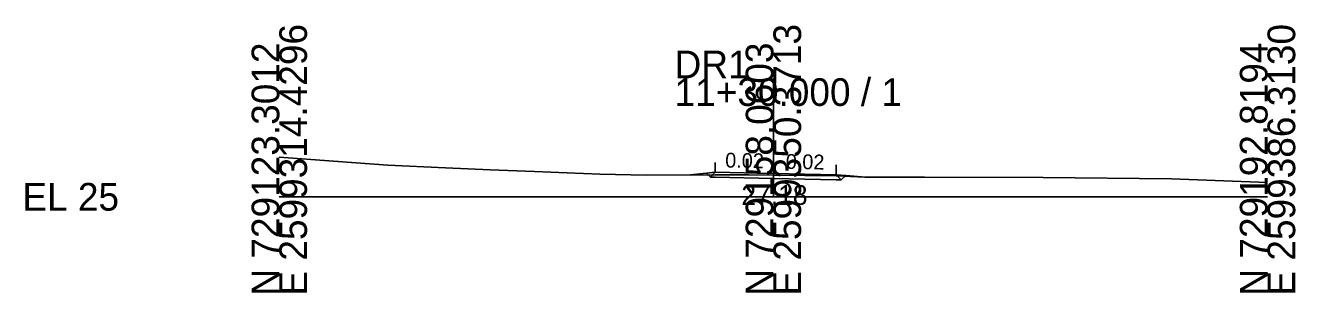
# Model space of a CAD drawing. Extents: x -26 to 1162, y -10 to 9515.
# Drawn here: x -25.7 to 102.8, y 6490.3 to 6517.3 of the extents above; entities that cross this region are included whole.
import ezdxf

# ---------------------------------------------------------------- set-up
doc = ezdxf.new("R2010")
doc.units = 0
for name, color, linetype in [('Exist Cross Section Cell', 7, 'Continuous'), ('Exist XS Center Line Elevation Label', 7, 'Continuous'), ('Exist XS Ground Line', 7, 'Continuous'), ('Prop XS Dump Level', 7, 'Continuous'), ('Prop XS EOT Tick Mark', 7, 'Continuous'), ('Prop XS Finish Grade', 7, 'Continuous'), ('Prop XS Finish Grade Earthwork', 7, 'Continuous'), ('Prop XS Finish Grade Pavement', 7, 'Continuous'), ('Prop XS Pvmt Edge Slope', 7, 'Continuous'), ('Prop XS SE Text', 7, 'Continuous'), ('Prop XS Subgrade Earthwork', 7, 'Continuous')]:
    doc.layers.add(name, color=color, linetype=linetype)

msp = doc.modelspace()

# ---------------------------------------------------------------- linework, layer by layer
at = {"layer": 'Exist Cross Section Cell'}
for p, q in [((50, 6500), (50, 6511.99)), ((0, 6500), (50, 6500)), ((50, 6500), (100, 6500))]:
    msp.add_line(p, q, dxfattribs=at)
at = {"layer": 'Exist XS Ground Line'}
msp.add_lwpolyline([(0, 6504), (10.99, 6503.2), (16.83, 6502.94), (21.35, 6502.72), (25.84, 6502.56), (32.44, 6502.28), (37.16, 6502.2), (44.12, 6502.23), (47.48, 6502.21), (50, 6502.18), (56.36, 6502.11), (59.24, 6502), (62.83, 6501.99), (65.29, 6501.99), (77.28, 6501.94), (90.28, 6501.83), (100, 6501.46)], dxfattribs=at)
at = {"layer": 'Prop XS Dump Level'}
for p, q in [((50, 6502.36), (44.11, 6502.48)), ((44.11, 6502.48), (50, 6502.36)), ((56.35, 6502.23), (50, 6502.36)), ((50, 6502.36), (56.35, 6502.23))]:
    msp.add_line(p, q, dxfattribs=at)
at = {"layer": 'Prop XS EOT Tick Mark'}
for p, q in [((44.11, 6502.48), (44.11, 6503.48)), ((56.35, 6502.23), (56.35, 6503.23))]:
    msp.add_line(p, q, dxfattribs=at)
at = {"layer": 'Prop XS Finish Grade'}
for p, q in [((44.11, 6502.48), (43.22, 6502.39)), ((56.35, 6502.23), (57.33, 6502.15))]:
    msp.add_line(p, q, dxfattribs=at)
at = {"layer": 'Prop XS Finish Grade Earthwork'}
for p, q in [((43.22, 6502.39), (41.57, 6502.22)), ((57.33, 6502.15), (59.31, 6502))]:
    msp.add_line(p, q, dxfattribs=at)
at = {"layer": 'Prop XS Finish Grade Pavement'}
for p, q in [((44.11, 6502.48), (50, 6502.36)), ((50, 6502.36), (56.35, 6502.23))]:
    msp.add_line(p, q, dxfattribs=at)
at = {"layer": 'Prop XS Pvmt Edge Slope'}
for p, q in [((44.11, 6502.48), (43.62, 6501.99)), ((43.22, 6502.39), (43.62, 6501.99)), ((56.35, 6502.23), (56.86, 6501.72)), ((57.33, 6502.15), (56.86, 6501.72))]:
    msp.add_line(p, q, dxfattribs=at)
at = {"layer": 'Prop XS Subgrade Earthwork'}
for p, q in [((43.22, 6502.39), (43.62, 6501.99)), ((44.11, 6501.98), (43.62, 6501.99)), ((50, 6501.86), (44.11, 6501.98)), ((56.35, 6501.73), (50, 6501.86)), ((56.35, 6501.73), (56.86, 6501.72)), ((56.86, 6501.72), (57.33, 6502.15))]:
    msp.add_line(p, q, dxfattribs=at)

# ---------------------------------------------------------------- texts
at = {"layer": 'Exist Cross Section Cell'}
for s, p in [('E 2599314.4296', (2.8, 6490)), ('E 2599350.3713', (52.8, 6490)), ('E 2599386.3130', (102.8, 6490)), ('N 729123.3012', (0, 6490)), ('N 729158.0603', (50, 6490)), ('N 729192.8194', (100, 6490))]:
    msp.add_text(s, height=2.8, rotation=90, dxfattribs=at).set_placement(p)
for s, p in [('DR1', (40, 6511.99)), ('11+30.000 / 1', (40, 6509.19)), ('EL 25', (-26, 6498.6))]:
    msp.add_text(s, height=2.8, dxfattribs=at).set_placement(p)
at = {"layer": 'Exist XS Center Line Elevation Label'}
msp.add_text('27.18', height=2, dxfattribs=at).set_placement((46.76, 6499.18))
at = {"layer": 'Prop XS SE Text'}
for p in [(45.11, 6502.96), (51.24, 6502.83)]:
    msp.add_text('0.02', height=1.5, rotation=358.8542, dxfattribs=at).set_placement(p)

doc.saveas('drawing.dxf')
